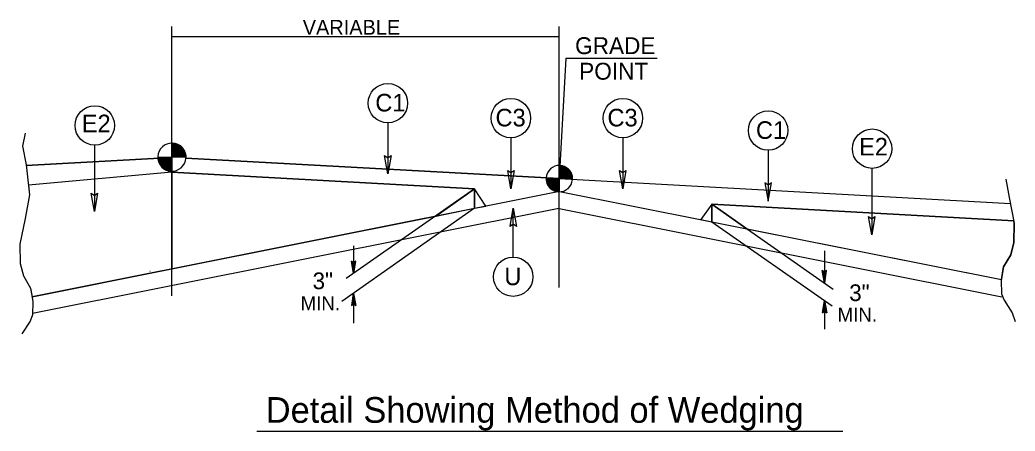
# Model space of a CAD drawing. Extents: x 1904401 to 1905163, y 193929 to 194736.
# Drawn here: x 1905090.1 to 1905162.5, y 194576.8 to 194606.8 of the extents above; entities that cross this region are included whole.
import ezdxf

# ---------------------------------------------------------------- set-up
doc = ezdxf.new("R2010")
doc.units = 0
for name, color, linetype in [('Old_Level_1', 7, 'Continuous'), ('Old_Level_11', 7, 'Continuous'), ('Old_Level_20', 7, 'Continuous'), ('Old_Level_21', 7, 'Continuous'), ('Old_Level_3', 7, 'Continuous'), ('Prop Shade Medium', 7, 'Continuous'), ('Typical Detail Wedge1 CELL', 7, 'Continuous'), ('Typical Grade Point Symbol CELL', 7, 'Continuous')]:
    doc.layers.add(name, color=color, linetype=linetype)

msp = doc.modelspace()

# ---------------------------------------------------------------- linework, layer by layer
at = {"layer": 'Old_Level_1'}
for p, q in [((1905129.322, 194595.238), (1905129.322, 194596.196)), ((1905128.363, 194595.238), (1905129.322, 194595.238)), ((1905129.316, 194594.279), (1905129.316, 194595.227)), ((1905129.322, 194595.238), (1905129.322, 194594.279)), ((1905130.282, 194595.238), (1905129.322, 194595.238)), ((1905129.322, 194594.279), (1905129.322, 194595.238)), ((1905123.159, 194594.491), (1905113.817, 194587.949)), ((1905123.159, 194593.075), (1905113.501, 194586.277)), ((1905140.427, 194593.379), (1905149.263, 194587.19)), ((1905140.427, 194592.099), (1905149.177, 194585.974)), ((1905114.343, 194590.35), (1905114.343, 194588.316)), ((1905148.618, 194589.982), (1905148.618, 194587.643)), ((1905114.343, 194588.316), (1905114.184, 194589.211)), ((1905114.343, 194589.096), (1905114.184, 194589.211)), ((1905114.343, 194588.316), (1905114.206, 194589.196)), ((1905114.231, 194589.178), (1905114.343, 194588.316)), ((1905114.343, 194588.316), (1905114.254, 194589.162)), ((1905114.276, 194589.146), (1905114.343, 194588.316)), ((1905114.343, 194588.316), (1905114.298, 194589.13)), ((1905114.321, 194589.113), (1905114.343, 194588.316)), ((1905114.343, 194588.316), (1905114.501, 194589.211)), ((1905114.501, 194589.211), (1905114.343, 194589.096)), ((1905114.478, 194589.196), (1905114.343, 194588.316)), ((1905114.343, 194588.316), (1905114.456, 194589.178)), ((1905114.433, 194589.162), (1905114.343, 194588.316)), ((1905114.343, 194588.316), (1905114.41, 194589.146)), ((1905114.389, 194589.13), (1905114.343, 194588.316)), ((1905114.343, 194588.316), (1905114.366, 194589.113)), ((1905114.343, 194589.096), (1905114.343, 194588.316)), ((1905148.618, 194587.643), (1905148.46, 194588.539)), ((1905148.618, 194588.422), (1905148.46, 194588.539)), ((1905148.618, 194587.643), (1905148.776, 194588.539)), ((1905148.776, 194588.539), (1905148.618, 194588.422)), ((1905148.618, 194587.643), (1905148.482, 194588.522)), ((1905148.504, 194588.505), (1905148.618, 194587.643)), ((1905148.618, 194587.643), (1905148.527, 194588.488)), ((1905148.55, 194588.471), (1905148.618, 194587.643)), ((1905148.618, 194587.643), (1905148.572, 194588.456)), ((1905148.594, 194588.439), (1905148.618, 194587.643)), ((1905148.752, 194588.522), (1905148.618, 194587.643)), ((1905148.618, 194587.643), (1905148.73, 194588.505)), ((1905148.707, 194588.488), (1905148.618, 194587.643)), ((1905148.618, 194587.643), (1905148.685, 194588.471)), ((1905148.662, 194588.456), (1905148.618, 194587.643)), ((1905148.618, 194587.643), (1905148.641, 194588.439)), ((1905148.618, 194588.422), (1905148.618, 194587.643)), ((1905114.351, 194586.874), (1905114.192, 194585.978)), ((1905114.216, 194585.995), (1905114.351, 194586.874)), ((1905114.351, 194586.874), (1905114.238, 194586.011)), ((1905114.261, 194586.028), (1905114.351, 194586.874)), ((1905114.351, 194586.874), (1905114.283, 194586.045)), ((1905114.306, 194586.061), (1905114.351, 194586.874)), ((1905114.351, 194586.874), (1905114.328, 194586.077)), ((1905114.351, 194586.874), (1905114.351, 194584.697)), ((1905114.351, 194586.874), (1905114.508, 194585.978)), ((1905114.351, 194586.094), (1905114.351, 194586.874)), ((1905114.373, 194586.077), (1905114.351, 194586.874)), ((1905114.351, 194586.874), (1905114.396, 194586.061)), ((1905114.419, 194586.045), (1905114.351, 194586.874)), ((1905114.351, 194586.874), (1905114.441, 194586.028)), ((1905114.463, 194586.011), (1905114.351, 194586.874)), ((1905114.351, 194586.874), (1905114.486, 194585.995)), ((1905114.192, 194585.978), (1905114.351, 194586.094)), ((1905114.351, 194586.094), (1905114.508, 194585.978)), ((1905148.63, 194586.356), (1905148.472, 194585.461)), ((1905148.494, 194585.479), (1905148.63, 194586.356)), ((1905148.63, 194586.356), (1905148.516, 194585.494)), ((1905148.539, 194585.512), (1905148.63, 194586.356)), ((1905148.63, 194586.356), (1905148.562, 194585.528)), ((1905148.584, 194585.544), (1905148.63, 194586.356)), ((1905148.63, 194586.356), (1905148.606, 194585.56)), ((1905148.63, 194586.356), (1905148.63, 194584.264)), ((1905148.63, 194586.356), (1905148.788, 194585.461)), ((1905148.63, 194585.577), (1905148.63, 194586.356)), ((1905148.653, 194585.56), (1905148.63, 194586.356)), ((1905148.63, 194586.356), (1905148.674, 194585.544)), ((1905148.697, 194585.528), (1905148.63, 194586.356)), ((1905148.63, 194586.356), (1905148.719, 194585.512)), ((1905148.742, 194585.494), (1905148.63, 194586.356)), ((1905148.63, 194586.356), (1905148.764, 194585.479)), ((1905148.472, 194585.461), (1905148.63, 194585.577)), ((1905148.63, 194585.577), (1905148.788, 194585.461))]:
    msp.add_line(p, q, dxfattribs=at)
for points in [[(1905129.331, 194596.196), (1905129.331, 194596.196), (1905129.331, 194595.238)], [(1905129.35, 194596.196), (1905129.35, 194595.238)], [(1905129.37, 194596.196), (1905129.37, 194595.238)], [(1905129.389, 194596.195), (1905129.389, 194595.238)], [(1905129.409, 194596.194), (1905129.409, 194595.238)], [(1905129.427, 194596.191), (1905129.427, 194595.238)], [(1905129.447, 194596.19), (1905129.447, 194595.238)], [(1905129.465, 194596.186), (1905129.465, 194595.238)], [(1905129.485, 194596.183), (1905129.485, 194595.238)], [(1905129.504, 194596.179), (1905129.504, 194595.238)], [(1905129.523, 194596.177), (1905129.523, 194595.238)], [(1905129.544, 194596.172), (1905129.544, 194595.238)], [(1905129.562, 194596.167), (1905129.562, 194595.238)], [(1905129.581, 194596.161), (1905129.581, 194595.238)], [(1905129.599, 194596.156), (1905129.599, 194595.238)], [(1905129.618, 194596.15), (1905129.618, 194595.238)], [(1905129.638, 194596.143), (1905129.638, 194595.238)], [(1905129.658, 194596.137), (1905129.658, 194595.238)], [(1905129.677, 194596.129), (1905129.677, 194595.238)], [(1905129.697, 194596.122), (1905129.695, 194595.238)], [(1905129.716, 194596.113), (1905129.716, 194595.238)], [(1905129.734, 194596.105), (1905129.734, 194595.238)], [(1905129.753, 194596.095), (1905129.753, 194595.238)], [(1905129.773, 194596.085), (1905129.773, 194595.238)], [(1905129.792, 194596.073), (1905129.792, 194595.238)], [(1905129.812, 194596.062), (1905129.812, 194595.238)], [(1905129.831, 194596.051), (1905129.83, 194595.238)], [(1905129.85, 194596.04), (1905129.85, 194595.238)], [(1905129.868, 194596.026), (1905129.868, 194595.238)], [(1905129.887, 194596.012), (1905129.887, 194595.238)], [(1905129.907, 194595.998), (1905129.907, 194595.238)], [(1905129.926, 194595.983), (1905129.926, 194595.238)], [(1905129.946, 194595.967), (1905129.946, 194595.238)], [(1905129.965, 194595.951), (1905129.964, 194595.238)], [(1905129.985, 194595.932), (1905129.985, 194595.238)], [(1905130.002, 194595.914), (1905130.002, 194595.238)], [(1905130.022, 194595.894), (1905130.022, 194595.238)], [(1905130.041, 194595.871), (1905130.041, 194595.238)], [(1905130.06, 194595.85), (1905130.06, 194595.238)], [(1905130.081, 194595.826), (1905130.081, 194595.238)], [(1905130.1, 194595.801), (1905130.098, 194595.238)], [(1905128.368, 194595.238), (1905128.368, 194595.133)], [(1905128.388, 194595.238), (1905128.388, 194595.021)], [(1905128.408, 194595.238), (1905128.408, 194594.952)], [(1905128.427, 194595.238), (1905128.427, 194594.896)], [(1905128.444, 194595.238), (1905128.444, 194594.848)], [(1905128.464, 194595.238), (1905128.464, 194594.809)], [(1905128.482, 194595.238), (1905128.482, 194594.773)], [(1905128.503, 194595.238), (1905128.503, 194594.739)], [(1905128.522, 194595.238), (1905128.522, 194594.71)], [(1905128.542, 194595.238), (1905128.542, 194594.68)], [(1905128.561, 194595.238), (1905128.561, 194594.655)], [(1905128.579, 194595.238), (1905128.579, 194594.631)], [(1905128.598, 194595.238), (1905128.598, 194594.608)], [(1905128.617, 194595.238), (1905128.617, 194594.586)], [(1905128.637, 194595.238), (1905128.637, 194594.567)], [(1905128.656, 194595.238), (1905128.656, 194594.549)], [(1905128.676, 194595.238), (1905128.676, 194594.529)], [(1905128.695, 194595.238), (1905128.694, 194594.513)], [(1905128.713, 194595.238), (1905128.713, 194594.496)], [(1905128.732, 194595.238), (1905128.732, 194594.482)], [(1905128.751, 194595.238), (1905128.751, 194594.467)], [(1905128.772, 194595.238), (1905128.772, 194594.454)], [(1905128.79, 194595.238), (1905128.79, 194594.44)], [(1905128.81, 194595.238), (1905128.81, 194594.427)], [(1905128.829, 194595.238), (1905128.828, 194594.415)], [(1905128.847, 194595.238), (1905128.847, 194594.404)], [(1905128.866, 194595.238), (1905128.866, 194594.394)], [(1905128.885, 194595.238), (1905128.885, 194594.383)], [(1905128.905, 194595.238), (1905128.905, 194594.374)], [(1905128.925, 194595.238), (1905128.925, 194594.365)], [(1905128.945, 194595.238), (1905128.945, 194594.356)], [(1905128.964, 194595.238), (1905128.963, 194594.349)], [(1905128.982, 194595.238), (1905128.982, 194594.342)], [(1905129.002, 194595.238), (1905129.002, 194594.333)], [(1905129.02, 194595.238), (1905129.02, 194594.328)], [(1905129.04, 194595.238), (1905129.04, 194594.322)], [(1905129.059, 194595.238), (1905129.059, 194594.316)], [(1905129.079, 194595.238), (1905129.079, 194594.311)], [(1905129.098, 194595.238), (1905129.097, 194594.305)], [(1905129.116, 194595.238), (1905129.116, 194594.302)], [(1905129.136, 194595.238), (1905129.135, 194594.298)], [(1905129.154, 194595.238), (1905129.154, 194594.294)], [(1905129.174, 194595.238), (1905129.174, 194594.292)], [(1905129.193, 194595.238), (1905129.193, 194594.287)], [(1905129.214, 194595.238), (1905129.214, 194594.286)], [(1905129.232, 194595.238), (1905129.231, 194594.283)], [(1905129.25, 194595.238), (1905129.25, 194594.282)], [(1905129.27, 194595.238), (1905129.269, 194594.28)], [(1905129.289, 194595.238), (1905129.289, 194594.28)], [(1905129.309, 194595.238), (1905129.309, 194594.279), (1905129.309, 194594.279)], [(1905130.118, 194595.775), (1905130.118, 194595.238)], [(1905130.136, 194595.743), (1905130.136, 194595.238)], [(1905130.155, 194595.711), (1905130.155, 194595.238)], [(1905130.175, 194595.676), (1905130.175, 194595.238)], [(1905130.195, 194595.636), (1905130.195, 194595.238)], [(1905130.214, 194595.591), (1905130.214, 194595.238)], [(1905130.233, 194595.537), (1905130.233, 194595.238)], [(1905130.253, 194595.472), (1905130.253, 194595.238)], [(1905130.271, 194595.374), (1905130.271, 194595.238)]]:
    msp.add_lwpolyline(points, dxfattribs=at)
for start, end in [(358.00034, 356.17131), (359.99048, 89.99048), (179.99048, 268.71864), (269.65334, 269.99048)]:
    msp.add_arc((1905129.322, 194595.238), 0.959, start, end, dxfattribs=at)
at = {"layer": 'Old_Level_11'}
for p, q in [((1905116.841, 194599.305), (1905116.841, 194595.596)), ((1905125.8, 194598.215), (1905125.8, 194594.506)), ((1905133.949, 194598.215), (1905133.949, 194594.506)), ((1905095.475, 194597.679), (1905095.475, 194592.84)), ((1905144.525, 194597.305), (1905144.525, 194593.596)), ((1905090.521, 194596.207), (1905101.109, 194596.789)), ((1905129.318, 194595.238), (1905102.136, 194596.733)), ((1905152.066, 194595.987), (1905152.066, 194591.148)), ((1905129.318, 194595.238), (1905162.159, 194593.435)), ((1905123.159, 194594.491), (1905123.159, 194593.075)), ((1905125.968, 194589.522), (1905125.968, 194593.073)), ((1905140.427, 194593.379), (1905140.427, 194592.099)), ((1905107.293, 194576.828), (1905149.962, 194576.828))]:
    msp.add_line(p, q, dxfattribs=at)
for points in [[(1905117.07, 194596.925), (1905116.841, 194595.596), (1905116.605, 194596.933), (1905116.841, 194596.763)], [(1905126.029, 194595.835), (1905125.8, 194594.506), (1905125.564, 194595.842), (1905125.8, 194595.673)], [(1905134.178, 194595.835), (1905133.949, 194594.506), (1905133.712, 194595.842), (1905133.949, 194595.673)], [(1905144.296, 194594.925), (1905144.525, 194593.596), (1905144.761, 194594.932), (1905144.525, 194594.763)], [(1905095.704, 194594.169), (1905095.475, 194592.84), (1905095.239, 194594.176), (1905095.475, 194594.006)], [(1905125.738, 194591.744), (1905125.968, 194593.073), (1905126.204, 194591.737), (1905125.968, 194591.907)], [(1905152.295, 194592.476), (1905152.066, 194591.148), (1905151.829, 194592.484), (1905152.066, 194592.314)]]:
    msp.add_lwpolyline(points, close=True, dxfattribs=at)
for centre in [(1905116.841, 194600.74), (1905125.8, 194599.65), (1905133.949, 194599.65), (1905095.502, 194599.114), (1905144.525, 194598.74), (1905152.092, 194597.422), (1905125.967, 194588.087)]:
    msp.add_circle(centre, 1.435, dxfattribs=at)
at = {"layer": 'Old_Level_3'}
for p, q in [((1905129.787, 194604.02), (1905129.318, 194595.238)), ((1905129.787, 194604.021), (1905136.456, 194604.021))]:
    msp.add_line(p, q, dxfattribs=at)
at = {"layer": 'Prop Shade Medium'}
for p, q in [((1905101.109, 194595.702), (1905090.669, 194594.763)), ((1905101.111, 194595.703), (1905101.109, 194595.702)), ((1905101.109, 194595.702), (1905101.109, 194588.665)), ((1905101.109, 194588.665), (1905101.109, 194595.702)), ((1905123.159, 194594.491), (1905101.111, 194595.703)), ((1905120.328, 194592.508), (1905123.159, 194594.491)), ((1905123.159, 194594.491), (1905120.328, 194592.508)), ((1905123.159, 194593.075), (1905123.159, 194594.491)), ((1905123.963, 194593.235), (1905123.159, 194594.491)), ((1905123.159, 194594.491), (1905123.159, 194593.075)), ((1905120.328, 194592.508), (1905123.159, 194593.075)), ((1905123.159, 194593.075), (1905123.963, 194593.235)), ((1905140.427, 194593.379), (1905139.635, 194592.257)), ((1905140.427, 194592.099), (1905140.427, 194593.379)), ((1905140.427, 194593.379), (1905140.427, 194592.099)), ((1905142.982, 194591.589), (1905140.427, 194593.379)), ((1905162.412, 194592.171), (1905140.427, 194593.379)), ((1905140.427, 194593.379), (1905142.982, 194591.589)), ((1905101.109, 194588.665), (1905120.328, 194592.508)), ((1905139.635, 194592.257), (1905140.427, 194592.099)), ((1905140.427, 194592.099), (1905142.982, 194591.589)), ((1905142.982, 194591.589), (1905161.511, 194587.893)), ((1905090.942, 194586.631), (1905101.109, 194588.665)), ((1905161.511, 194587.893), (1905161.669, 194588.797))]:
    msp.add_line(p, q, dxfattribs=at)
for points in [[(1905090.669, 194594.763), (1905090.743, 194594.057), (1905090.427, 194592.33), (1905090.054, 194590.457), (1905090.081, 194589.046), (1905090.313, 194588.153), (1905090.831, 194587.259), (1905090.942, 194586.631)], [(1905161.669, 194588.797), (1905162.189, 194589.691), (1905162.419, 194590.582), (1905162.448, 194591.994), (1905162.412, 194592.171)]]:
    msp.add_lwpolyline(points, dxfattribs=at)
at = {"layer": 'Typical Detail Wedge1 CELL'}
for p, q in [((1905101.109, 194596.789), (1905101.109, 194606.326)), ((1905129.318, 194587.295), (1905129.318, 194606.32)), ((1905101.109, 194605.596), (1905129.318, 194605.596)), ((1905101.109, 194596.789), (1905090.521, 194596.207)), ((1905101.109, 194596.789), (1905101.111, 194595.703)), ((1905102.136, 194596.733), (1905129.318, 194595.238)), ((1905101.111, 194595.703), (1905090.669, 194594.763)), ((1905101.109, 194586.697), (1905101.109, 194595.778)), ((1905101.115, 194595.778), (1905101.111, 194595.703)), ((1905101.111, 194595.703), (1905123.159, 194594.491)), ((1905129.318, 194595.238), (1905162.159, 194593.435)), ((1905123.963, 194593.235), (1905123.159, 194594.491)), ((1905129.341, 194594.311), (1905090.942, 194586.631)), ((1905129.341, 194594.311), (1905161.514, 194587.892)), ((1905129.289, 194593.065), (1905090.976, 194585.402)), ((1905129.318, 194593.065), (1905161.532, 194586.621)), ((1905140.427, 194593.379), (1905139.635, 194592.257)), ((1905140.427, 194593.379), (1905162.412, 194592.171))]:
    msp.add_line(p, q, dxfattribs=at)
for points in [[(1905090.427, 194598.549), (1905090.254, 194597.6), (1905090.514, 194596.246), (1905090.743, 194594.057), (1905090.427, 194592.33), (1905090.054, 194590.457), (1905090.081, 194589.046), (1905090.313, 194588.153), (1905090.831, 194587.259), (1905091.004, 194586.281), (1905090.974, 194585.302), (1905090.802, 194584.841), (1905090.198, 194583.921)], [(1905161.829, 194595.2), (1905162.074, 194593.864), (1905162.448, 194591.994), (1905162.419, 194590.582), (1905162.189, 194589.691), (1905161.669, 194588.797), (1905161.498, 194587.818), (1905161.526, 194586.839), (1905161.699, 194586.377), (1905162.303, 194585.456), (1905162.505, 194584.822)]]:
    msp.add_lwpolyline(points, dxfattribs=at)
msp.add_arc((1905099.521, 194588.437), 0.0292, 75.75829, 126.57458, dxfattribs=at)
at = {"layer": 'Typical Grade Point Symbol CELL'}
for p, q in [((1905101.115, 194596.801), (1905101.115, 194597.822)), ((1905100.093, 194596.801), (1905101.115, 194596.801)), ((1905101.109, 194595.778), (1905101.109, 194596.789)), ((1905102.14, 194596.801), (1905101.115, 194596.801)), ((1905101.115, 194595.778), (1905101.115, 194596.801)), ((1905101.115, 194596.801), (1905101.115, 194595.778))]:
    msp.add_line(p, q, dxfattribs=at)
for points in [[(1905101.125, 194597.822), (1905101.125, 194597.822), (1905101.125, 194596.801)], [(1905101.145, 194597.822), (1905101.145, 194596.801)], [(1905101.167, 194597.822), (1905101.167, 194596.801)], [(1905101.187, 194597.821), (1905101.187, 194596.801)], [(1905101.209, 194597.82), (1905101.209, 194596.801)], [(1905101.228, 194597.816), (1905101.228, 194596.801)], [(1905101.249, 194597.815), (1905101.249, 194596.801)], [(1905101.268, 194597.812), (1905101.268, 194596.801)], [(1905101.289, 194597.808), (1905101.289, 194596.801)], [(1905101.31, 194597.804), (1905101.31, 194596.801)], [(1905101.33, 194597.802), (1905101.33, 194596.801)], [(1905101.352, 194597.796), (1905101.352, 194596.801)], [(1905101.372, 194597.791), (1905101.371, 194596.801)], [(1905101.392, 194597.785), (1905101.392, 194596.801)], [(1905101.411, 194597.779), (1905101.411, 194596.801)], [(1905101.432, 194597.773), (1905101.432, 194596.801)], [(1905101.453, 194597.766), (1905101.453, 194596.801)], [(1905101.474, 194597.759), (1905101.474, 194596.801)], [(1905101.495, 194597.751), (1905101.495, 194596.801)], [(1905101.515, 194597.742), (1905101.514, 194596.801)], [(1905101.536, 194597.733), (1905101.536, 194596.801)], [(1905101.555, 194597.724), (1905101.555, 194596.801)], [(1905101.575, 194597.715), (1905101.575, 194596.801)], [(1905101.596, 194597.703), (1905101.596, 194596.801)], [(1905101.617, 194597.691), (1905101.617, 194596.801)], [(1905101.638, 194597.679), (1905101.638, 194596.801)], [(1905101.659, 194597.667), (1905101.657, 194596.801)], [(1905101.679, 194597.655), (1905101.679, 194596.801)], [(1905101.698, 194597.641), (1905101.698, 194596.801)], [(1905101.718, 194597.625), (1905101.718, 194596.801)], [(1905101.74, 194597.611), (1905101.74, 194596.801)], [(1905101.76, 194597.596), (1905101.76, 194596.801)], [(1905101.781, 194597.578), (1905101.781, 194596.801)], [(1905101.802, 194597.56), (1905101.801, 194596.799)], [(1905101.822, 194597.541), (1905101.822, 194596.801)], [(1905101.841, 194597.522), (1905101.841, 194596.799)], [(1905101.861, 194597.5), (1905101.861, 194596.799)], [(1905101.883, 194597.476), (1905101.883, 194596.801)], [(1905101.903, 194597.452), (1905101.903, 194596.799)], [(1905101.925, 194597.427), (1905101.925, 194596.799)], [(1905101.945, 194597.401), (1905101.944, 194596.801)], [(1905101.965, 194597.372), (1905101.965, 194596.799)], [(1905101.984, 194597.339), (1905101.984, 194596.799)], [(1905102.005, 194597.306), (1905102.005, 194596.801)], [(1905102.026, 194597.267), (1905102.026, 194596.799)], [(1905100.099, 194596.801), (1905100.099, 194596.688)], [(1905100.119, 194596.801), (1905100.119, 194596.569)], [(1905100.14, 194596.801), (1905100.14, 194596.495)], [(1905100.161, 194596.801), (1905100.161, 194596.435)], [(1905100.18, 194596.801), (1905100.18, 194596.384)], [(1905100.2, 194596.801), (1905100.2, 194596.342)], [(1905100.22, 194596.801), (1905100.22, 194596.304)], [(1905100.242, 194596.801), (1905100.242, 194596.268)], [(1905100.262, 194596.801), (1905100.262, 194596.236)], [(1905100.284, 194596.801), (1905100.284, 194596.205)], [(1905100.304, 194596.801), (1905100.304, 194596.179)], [(1905100.323, 194596.801), (1905100.323, 194596.153)], [(1905100.343, 194596.801), (1905100.343, 194596.127)], [(1905100.364, 194596.801), (1905100.364, 194596.105)], [(1905100.385, 194596.801), (1905100.385, 194596.084)], [(1905100.405, 194596.801), (1905100.405, 194596.065)], [(1905100.427, 194596.801), (1905100.427, 194596.044)], [(1905100.447, 194596.801), (1905100.446, 194596.026)], [(1905100.466, 194596.801), (1905100.466, 194596.008)], [(1905100.486, 194596.801), (1905100.486, 194595.994)], [(1905100.507, 194596.801), (1905100.507, 194595.978)], [(1905100.528, 194596.801), (1905100.528, 194595.964)], [(1905100.549, 194596.801), (1905100.549, 194595.948)], [(1905100.57, 194596.801), (1905100.57, 194595.935)], [(1905100.59, 194596.801), (1905100.589, 194595.922)], [(1905100.609, 194596.801), (1905100.609, 194595.91)], [(1905100.63, 194596.801), (1905100.63, 194595.9)], [(1905100.65, 194596.801), (1905100.65, 194595.889)], [(1905100.671, 194596.801), (1905100.671, 194595.878)], [(1905100.692, 194596.801), (1905100.692, 194595.87)], [(1905100.713, 194596.801), (1905100.713, 194595.859)], [(1905100.734, 194596.801), (1905100.732, 194595.852)], [(1905100.753, 194596.801), (1905100.753, 194595.845)], [(1905100.774, 194596.801), (1905100.774, 194595.835)], [(1905100.793, 194596.801), (1905100.793, 194595.829)], [(1905100.815, 194596.801), (1905100.815, 194595.823)], [(1905100.835, 194596.801), (1905100.835, 194595.817)], [(1905100.856, 194596.801), (1905100.856, 194595.811)], [(1905100.877, 194596.801), (1905100.876, 194595.805)], [(1905100.896, 194596.801), (1905100.896, 194595.802)], [(1905100.917, 194596.801), (1905100.916, 194595.797)], [(1905100.936, 194596.801), (1905100.936, 194595.793)], [(1905100.958, 194596.801), (1905100.958, 194595.791)], [(1905100.978, 194596.801), (1905100.978, 194595.786)], [(1905101, 194596.801), (1905101, 194595.785)], [(1905101.02, 194596.801), (1905101.019, 194595.781)], [(1905101.039, 194596.801), (1905101.039, 194595.78)], [(1905101.061, 194596.801), (1905101.059, 194595.779)], [(1905101.08, 194596.801), (1905101.08, 194595.779)], [(1905101.101, 194596.801), (1905101.101, 194595.778), (1905101.101, 194595.778)], [(1905102.046, 194597.224), (1905102.046, 194596.799)], [(1905102.068, 194597.177), (1905102.068, 194596.801)], [(1905102.087, 194597.119), (1905102.087, 194596.799)], [(1905102.109, 194597.05), (1905102.109, 194596.799)], [(1905102.128, 194596.945), (1905102.128, 194596.801)]]:
    msp.add_lwpolyline(points, dxfattribs=at)
for start, end in [(358.00034, 356.17131), (359.99048, 89.99048), (179.99048, 268.71864), (269.65334, 269.99048)]:
    msp.add_arc((1905101.115, 194596.8), 1.023, start, end, dxfattribs=at)

# ---------------------------------------------------------------- texts
at = {"layer": 'Old_Level_11'}
for s, p in [('GRADE', (1905130.473, 194604.317)), ('POINT', (1905130.769, 194602.453))]:
    msp.add_text(s, height=1.23, dxfattribs=at).set_placement(p)
at = {"layer": 'Old_Level_20'}
for s, height, p in [('C1', 1.2846, (1905115.928, 194600.134)), ('C3', 1.2846, (1905124.679, 194599.044)), ('C3', 1.2846, (1905132.828, 194599.044)), ('E2', 1.2846, (1905094.558, 194598.619)), ('C1', 1.2846, (1905143.638, 194598.134)), ('E2', 1.2846, (1905151.148, 194596.927)), ('U', 1.285, (1905125.325, 194587.47)), ('3"', 1.2171, (1905111.363, 194587.179)), ('3"', 1.2171, (1905150.43, 194586.31))]:
    msp.add_text(s, height=height, dxfattribs=at).set_placement(p)
at = {"layer": 'Old_Level_21'}
for s, height, p in [('MIN.', 1.017, (1905110.491, 194585.647)), ('MIN.', 1.017, (1905149.583, 194584.812)), ('Detail Showing Method of Wedging', 1.875, (1905107.95, 194577.435))]:
    msp.add_text(s, height=height, dxfattribs=at).set_placement(p)
at = {"layer": 'Typical Detail Wedge1 CELL'}
msp.add_text('VARIABLE', height=1.0846, dxfattribs=at).set_placement((1905110.646, 194605.728))

doc.saveas('drawing.dxf')
